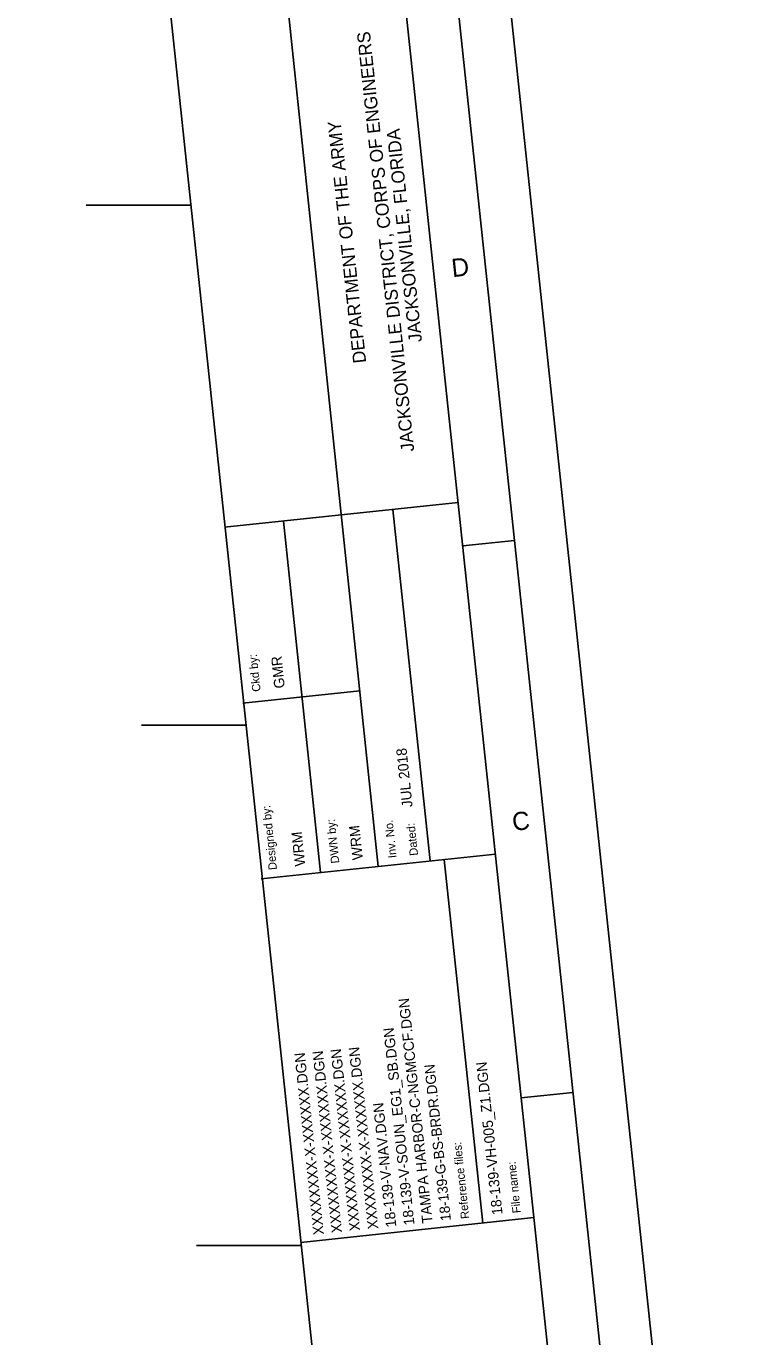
# Model space of a CAD drawing. Extents: x 344453 to 349187, y 1184529 to 1188374.
# Drawn here: x 348489 to 349187, y 1185912 to 1187172 of the extents above; entities that cross this region are included whole.
import ezdxf

# ---------------------------------------------------------------- set-up
doc = ezdxf.new("R2010")
doc.units = 0
for name, color, linetype in [('G-ANNO-NPLT', 7, 'Continuous'), ('G-ANNO-TEXT-DRWG', 7, 'Continuous'), ('G-ANNO-TEXT-PROJ', 7, 'Continuous'), ('G-ANNO-TEXT-TTLB', 7, 'Continuous'), ('G-ANNO-TTLB', 7, 'Continuous'), ('V-TOPO-COOR-STAT', 7, 'Continuous')]:
    doc.layers.add(name, color=color, linetype=linetype)

msp = doc.modelspace()

# ---------------------------------------------------------------- linework, layer by layer
at = {"layer": 'G-ANNO-NPLT'}
msp.add_lwpolyline([(344453.5, 1187909.7), (348828.9, 1188373.5), (349187.3, 1184992.5), (344811.8, 1184528.7)], close=True, dxfattribs=at)
at = {"layer": 'G-ANNO-TTLB'}
for p, q in [((348516.3, 1188239.8), (348853.6, 1185057.7)), ((348827.5, 1186364.4), (348737.6, 1187219.2)), ((348679.7, 1186690.3), (348904.3, 1186714.1)), ((348841.7, 1186707.4), (348877.5, 1186369.7)), ((348771.9, 1186358.5), (348736.4, 1186696.3)), ((348958.4, 1186677.6), (348908.7, 1186672.4)), ((348697.6, 1186521.4), (348809.8, 1186533.3)), ((348715.1, 1186352.4), (348940.1, 1186376.3)), ((348891, 1186371.1), (348928.1, 1186021.7)), ((349014.6, 1186147.3), (348964.9, 1186142)), ((348753.3, 1186003.1), (348977.1, 1186026.9))]:
    msp.add_line(p, q, dxfattribs=at)
for points in [[(344856.3, 1184583.7), (349132.3, 1185036.9), (348784.5, 1188318.5), (344508.5, 1187865.3)], [(348740, 1188263.6), (344638, 1187828.7), (344975.3, 1184646.6), (349077.3, 1185081.4)]]:
    msp.add_lwpolyline(points, close=True, dxfattribs=at)
at = {"layer": 'V-TOPO-COOR-STAT'}
for p, q in [((348547.1, 1187000), (348647.7, 1187000)), ((348600.1, 1186500), (348700.7, 1186500)), ((348653.1, 1186000), (348753.7, 1186000))]:
    msp.add_line(p, q, dxfattribs=at)

# ---------------------------------------------------------------- texts
at = {"layer": 'G-ANNO-TEXT-DRWG'}
for s, p in [('GMR', (348737.8, 1186536)), ('WRM', (348812.8, 1186371.2)), ('WRM', (348757.5, 1186365.1)), ('TAMPA HARBOR-C-NGMCCF.DGN', (348879.8, 1186021.9)), ('18-139-V-SOUN_EG1_SB.DGN', (348862.4, 1186020.1)), ('XXXXXXXX-X-XXXXXX.DGN', (348775.4, 1186010.9)), ('XXXXXXXX-X-XXXXXX.DGN', (348792.8, 1186012.7)), ('XXXXXXXX-X-XXXXXX.DGN', (348810.2, 1186014.6)), ('XXXXXXXX-X-XXXXXX.DGN', (348827.6, 1186016.4)), ('18-139-VH-005_Z1.DGN', (348947, 1186030.1)), ('18-139-V-NAV.DGN', (348845, 1186018.2))]:
    msp.add_text(s, height=10, rotation=96.0506, dxfattribs=at).set_placement(p)
at = {"layer": 'G-ANNO-TEXT-PROJ'}
for s, height, p in [('JUL 2018', 10, (348860.6, 1186421.7)), ('18-139-G-BS-BRDR.DGN', 9.8, (348897.4, 1186024.2))]:
    msp.add_text(s, height=height, rotation=96.0506, dxfattribs=at).set_placement(p)
at = {"layer": 'G-ANNO-TEXT-TTLB'}
for s, height, p in [('JACKSONVILLE DISTRICT, CORPS OF ENGINEERS', 12.5, (348862.2, 1186763.6)), ('DEPARTMENT OF THE ARMY', 12.5, (348816, 1186848.6)), ('JACKSONVILLE, FLORIDA', 12.5, (348869.6, 1186868.8)), ('Ckd by:', 8, (348714.6, 1186532.7)), ('Designed by:', 8, (348730.3, 1186361.4)), ('DWN by:', 8, (348790.2, 1186367.7)), ('Inv. No.', 8, (348845.2, 1186372.8)), ('Dated:', 8, (348865.8, 1186375.1)), ('Reference files:', 8, (348915, 1186026.1)), ('File name:', 8, (348964.6, 1186031.6))]:
    msp.add_text(s, height=height, rotation=96.0506, dxfattribs=at).set_placement(p)
at = {"layer": 'G-ANNO-TTLB'}
for s, p in [('D', (348898.8, 1186930.6)), ('C', (348957.1, 1186398.5))]:
    msp.add_text(s, height=17.5, rotation=6.0506, dxfattribs=at).set_placement(p)

doc.saveas('drawing.dxf')
